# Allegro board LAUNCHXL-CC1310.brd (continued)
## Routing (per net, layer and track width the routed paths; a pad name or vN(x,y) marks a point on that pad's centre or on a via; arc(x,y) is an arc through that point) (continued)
N949695: length 4.1
  TOP w0.15: U5.88 8.5,81 Y3.1 9,81.7 9.8,82.5 C33.1
N950083: length 5.9
  TOP w0.15: U5.9 8.5,62.9 R18.1 C32.1 C50.1 9.91,61.6 10.5,61 U6.3
N950235: length 2.1
  TOP w0.15: 5.6,81.4 R19.2 5.6,80.57 5.7,80.48 U5.95
N951001: length 2.2
  TOP w0.15: U5.63 19.96,77.4 20.96,78.4 R39.2
N951013: length 1.9
  TOP w0.15: U5.61 R29.1
N951017: length 2
  TOP w0.15: 19.2,77 20.46,77 20.96,77.5 R27.2
N952443: length 3.9
  TOP w0.15: 18.33,80.9 R31.1 ; 18.33,80.9 C46.1 ; 18.33,80.9 17.73,80.3 16.65,80.3 16.5,80.15 U5.68
N1004371: length 7.3
  TOP w0.15: U5.3 6.1,64.61 5.81,64.9 4.93,64.9 2.43,62.4 1.66,62.4 1,63.06 R23.2
N1004534: length 6.3
  TOP w0.15: U5.4 6.5,64.85 6.15,65.2 4.8,65.2 2.68,63.08 R25.2
N1013277: length 6.9
  TOP w0.15: U1.46 22.55,41.4 21.55,40.4 20.08,40.4 19.78,40.1 18.2,40.1 Y2.3
N1013855: length 3.7
  TOP w0.3: C22.1 24.6,37.08 L23.2 24.67,37.2 L22.2 24.67,38.47 24.4,38.75 U1.2
N1013859: length 3.7
  TOP w0.3: 23.7,38 L22.1 ; L22.1 23.75,38.55 23.9,38.7 U1.1 ; L22.1 23.75,37.23 C11.2 23.7,37.02 L12.1
N1013899: length 3.8
  TOP w0.3: 24.6,35.4 C22.2 24.6,34.75 24.2,34.35 23.7,34.85 L12.2 23.7,35.4
  TOP w0.4: 24.2,34.35 C12.1 L13.1
N1013931: length 1.7
  TOP w0.4: L13.2 C13.1 L14.1
N1013977: length 1.9
  TOP w0.4: 29.9,27.1 R12.2 C58.1 A1.1
N1014101: length 9.4
  TOP w0.15: C17.1 Y1.1 29.1,33.9 28.38,34.63 28.38,36.07 25.4,39.05 U1.4
N1014113: length 7.1
  TOP w0.15: C18.1 30.73,36.4 Y1.2 28.47,36.4 25.9,38.97 U1.5
N1018952: length 5.1
  TOP w0.15: U1.47 22.5,40.9 21.7,40.1 20.2,40.1 19,38.9 Y2.1
N1031635: length 1.8
  TOP w0.3: 9.5,89 9.5,88.21 10.11,87.6 CR6.1
  vias: v1(7.3,90.6) v1(7.7,89.3) v1(15.2,89.6) v1(15.6,90.5)
N1105722: length 0.9
  TOP w0.15: R15.1 CR1.2
N1105771: length 1
  TOP w0.15: R14.1 CR2.2
N1105824: length 1.8
  TOP w0.15: 17.4,31.5 R14.2 P6.1
N1106228: length 1.9
  TOP w0.15: P6.3 19.94,31.94 20,31.88 R15.2 20,31.4
N1176544: length 6.3
  TOP w0.15: J2.13 48.56,29.22 48.53,29.2 R46.1
N1176548: length 6.3
  TOP w0.15: J2.15 48.56,26.68 48.53,26.7 R47.1
N1176568: length 6.3
  TOP w0.15: R48.1 49.54,24.1 J2.17
N1177007: length 6.3
  TOP w0.15: R49.1 J2.19
N1288065: length 2.2
  TOP w0.15: SW2.3 R55.1
N1288098: length 1.3
  TOP w0.15: SW1.4 5.07,48.72 R56.1
N1384129: length 4.7
  TOP w0.15: R57.1 19.7,91.6 SW3.3
N1393569: length 1.4
  TOP w0.3: U1.23 30.62,45.4 31.1,45.88 C19.1
N1403554: length 3.8
  TOP w0.3: U1.3 24.9,38.97 25.4,38.47 25.4,37.73 25.5,37.63 L23.1 25.7,36.9 C21.1
N1414078: length 1.8
  TOP w0.4: C15.1 25.79,29.4 25.77,29.42 25.42,29.41 25.41,29.4 C14.1 24.79,29.4 24.78,29.41 24.43,29.42 24.26,29.42 L14.2
N1442334: length 0.8
  TOP w0.15: R59.1 39.6,33.3 U4.3
N1442341: length 0.9
  TOP w0.15: R60.1 39.1,36.9 U4.7
N1450387: length 4.1
  TOP w0.4: R13.1 29.9,28.9 C24.1 29.48,29.32 29.46,29.32 29.38,29.4 C15.2
N1456638: length 5.1
  TOP w0.4: R13.2 32.6,28 32.8,28.2 P11.1
N1467198: length 1.7
  TOP w0.15: R66.2 4.62,79.85 4.6,79.82 C59.1 U5.96
N10367920: length 1.2
  TOP w0.15: CR5.2 R25.1
N10368080: length 1.2
  TOP w0.15: CR4.2 R23.1

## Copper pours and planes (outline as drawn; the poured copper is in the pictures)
GND on TOP (solid shape): 30.9,15.7 12.9,15.7 12.9,12.7 48.9,12.7 48.9,5.7 12.9,5.7 12.9,2.7 48.9,2.7 48.9,0.7 10.9,0.7 10.9,7.7 46.9,7.7 46.9,10.7 10.9,10.7 10.9,17.7 28.9,17.7 28.9,24.7 30.9,24.7
GND on BOTTOM (solid shape): 30.9,15.7 12.9,15.7 12.9,12.7 48.9,12.7 48.9,5.7 12.9,5.7 12.9,2.7 48.9,2.7 48.9,0.7 10.9,0.7 10.9,7.7 46.9,7.7 46.9,10.7 10.9,10.7 10.9,17.7 28.9,17.7 28.9,24.7 30.9,24.7
GND on TOP: 52.5,90.2 52.5,94.8 57.04,94.8 57.72,94.52 58,93.84 58,90.2
GND on TOP: 0.5,25.9 0.5,44.5 0.76,46 1.49,47.34 2.7,50.8 1.49,54.26 0.97,55.09 0.64,56 0.67,56 0.5,57.3 0.5,93.84 0.78,94.52 1.46,94.8 6.5,94.8 6.5,91 6.5,93.6 8.1,93.6 8.1,91.5 10,91.5 10,93.6 12.8,93.6 12.8,91.5 14.7,91.5 14.7,93.6 16.3,93.6 16.3,94.8 57.04,94.8 57.72,94.52 58,93.84 58,56.6 57.83,56 57.86,56 57.53,55.08 57.01,54.26 55.8,50.8 57.01,47.34 57.74,46 58,44.5 58,25.9 37.6,25.9 37.6,30.3 26.4,30.3 26.4,38.4 21.9,38.4 21.9,25.9 ; 36 cut-outs
GND on TOP: 21.9,38.4 26.4,38.4 26.4,30.3 37.6,30.3 37.6,25.9 21.9,25.9
GND on TOP: 0.5,90.3 0.5,93.84 0.78,94.52 1.46,94.8 6.5,94.8 6.5,93.6 6.6,93.6 6.6,90.3
GND on BOTTOM: 53.27,90.21 53.27,94.81 57.01,94.81 57.69,94.53 57.97,93.85 57.97,90.21
GND on BOTTOM: 0.5,25.9 0.5,44.5 0.76,46 1.49,47.34 2.7,50.8 1.49,54.26 1.33,54.48 1.18,54.7 0.67,55.85 0.5,57.1 0.5,57.29 0.5,57.3 0.5,93.84 0.78,94.52 1.46,94.8 6.5,94.8 6.5,93.6 8.1,93.6 8.1,91.5 10,91.5 10,93.6 12.8,93.6 12.8,91.5 14.7,91.5 14.7,93.6 16.3,93.6 16.3,94.8 57.04,94.8 57.72,94.52 58,93.84 58,93.6 58,57.8 58,57.1 58,57.09 57.82,55.85 57.32,54.7 57.17,54.48 57.01,54.26 55.8,50.8 57.01,47.34 57.74,46 58,44.5 58,25.9 ; 1 cut-out
GND on BOTTOM: 0.51,90.29 0.51,93.83 0.79,94.51 1.47,94.79 5.11,94.79 5.11,90.29
GND on L2: 0.5,25.9 0.5,44.5 0.76,46 1.49,47.34 2.7,50.8 1.49,54.26 1.27,54.57 1.07,54.9 0.64,55.96 0.5,57.1 0.5,57.2 0.51,57.2 0.5,57.3 0.5,93.84 0.78,94.52 1.46,94.8 6.5,94.8 6.5,93.6 8.1,93.6 8.1,91.5 10,91.5 10,93.6 12.8,93.6 12.8,91.5 14.7,91.5 14.7,93.6 16.3,93.6 16.3,94.8 57.04,94.8 57.72,94.52 58,93.84 58,93.6 58,57.3 58,57.1 57.85,55.96 57.43,54.9 57.23,54.57 57.01,54.26 55.8,50.8 57.01,47.34 57.74,46 58,44.5 58,25.9 ; 2 cut-outs
USB_VBUS on L3: 10.3,89.9 12.4,89.9 14.9,87.4 14.9,86.3 14.3,85.7 8.9,85.7 7.9,86.7 7.9,87.5
XDS_VCC on L3: 3.4,84.2 21.1,84.2 23.1,82.2 23.1,68.6 14.6,60.1 7.5,60.1 1.1,66.5 1.1,81.9
N1031635 on TOP: 6.8,88.9 6.8,93.6 8.1,93.6 8.1,91.5 10,91.5 10,93.6 12.8,93.6 12.8,91.7 14.5,91.7 14.5,91.1 14.7,91.1 14.7,91.7 14.7,93.6 16,93.6 16,88.9 ; 1 cut-out
N1031635 on BOTTOM, L2: 6.8,88.9 6.8,93.6 8.1,93.6 8.1,91.5 10,91.5 10,93.6 12.8,93.6 12.8,91.5 14.7,91.5 14.7,93.6 16,93.6 16,88.9

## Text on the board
Ref Des/Silkscreen Bottom: J1 | 1 | 10 | 21 | 30 | J3 | J4 | 31 | 40 | 11 | 20 | J2 | DIO23 | DIO2 | DIO3 | DIO22 | DIO24 | DIO0 | DIO1 | DIO25 | DIO27 | DIO28 | DIO29 | DIO30 | DIO26 | DIO7 | DIO6 | DIO20 | DIO19 | DIO18 | BPRST | For evaluation only; not FCC approved for resale | NC | DIO9 | DIO8 | DIO12 | DIO11 | LPRST | DIO13 | DIO14 | DIO15 | DIO10 | DIO21 | DIO4 | DIO5 | TMS | TCK | DIO16 | DIO17 | www.ti.com/launchpad | >>LAUNCHXL-CC1310 | CC1310 LaunchPad
User.Comments: Pb
Ref Des/Silkscreen Top: J1 | 10 | 1 | 21 | 30 | J3 | J4 | 40 | 31 | 20 | 11 | J2 | DIO23 | DIO2 | DIO3 | DIO22 | DIO24 | DIO13 | BTN-1 | DIO26 | DIO29 | DIO25 | DIO27 | DIO28 | DIO0 | DIO30 | DIO1 | Red: | DIO6 | Green: | DIO7 | LEDs | CC-ANTENNA-DK | Mount for: | CC1310 In | Rev: 1.3 | XDS110 Out | BP | LP | DIO20 | DIO19 | DIO18 | BPRST | VSENSE | BTN-2 | DIO14 | Extern. | Pwr. | XDS110 | Power | NC | DIO12 | DIO11 | LPRST | DIO9 | DIO8 | DIO15 | DIO10 | DIO21 | DIO4 | DIO5 | DIO16 | DIO17 | TMS | TCK | RXD<< | TXD>> | R | Reset | TDI | TDO | SWO
XSECTION_CHART: L1: TOP CONDUCTOR - COPPER 0.035 MM | *  DIELECTRIC - FR-4 0.175 MM | L2: L2 PLANE - COPPER 0.035 MM | *  DIELECTRIC - FR-4 1.11 MM | L3: L3 PLANE - COPPER 0.035 MM | L4: BOTTOM CONDUCTOR - COPPER 0.035 MM | DESIGN CROSS SECTION CHART | ___________________________ | TOTAL THICKNESS 1.6 MM
User.6: FIGURE | SIZE | 0.2 | 0.201 | 1.05 | 1.1 | 3.2 | 0.899 | 1.001 | 1.3x0.6 | DRILL CHART: TOP to BOTTOM | ALL UNITS ARE IN MILLIMETERS | PLATED | NON-PLATED | QTY | 494 | 28 | 75 | 1 | 2 | 6 | 3 | 4
